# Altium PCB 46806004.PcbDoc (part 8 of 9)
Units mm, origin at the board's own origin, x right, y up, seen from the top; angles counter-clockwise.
Board outline 130 x 105 mm, 8 copper layers (Top Layer, P1-GND, L1-Signal, L2-Signal, L3-Signal, L4-Signal, P2-GND, Bottom Layer), stack 1.63 mm thick; 796 components, 496 nets, 2808 pads, 1195 vias.
Unrouted connection lines stored in the file: 1.
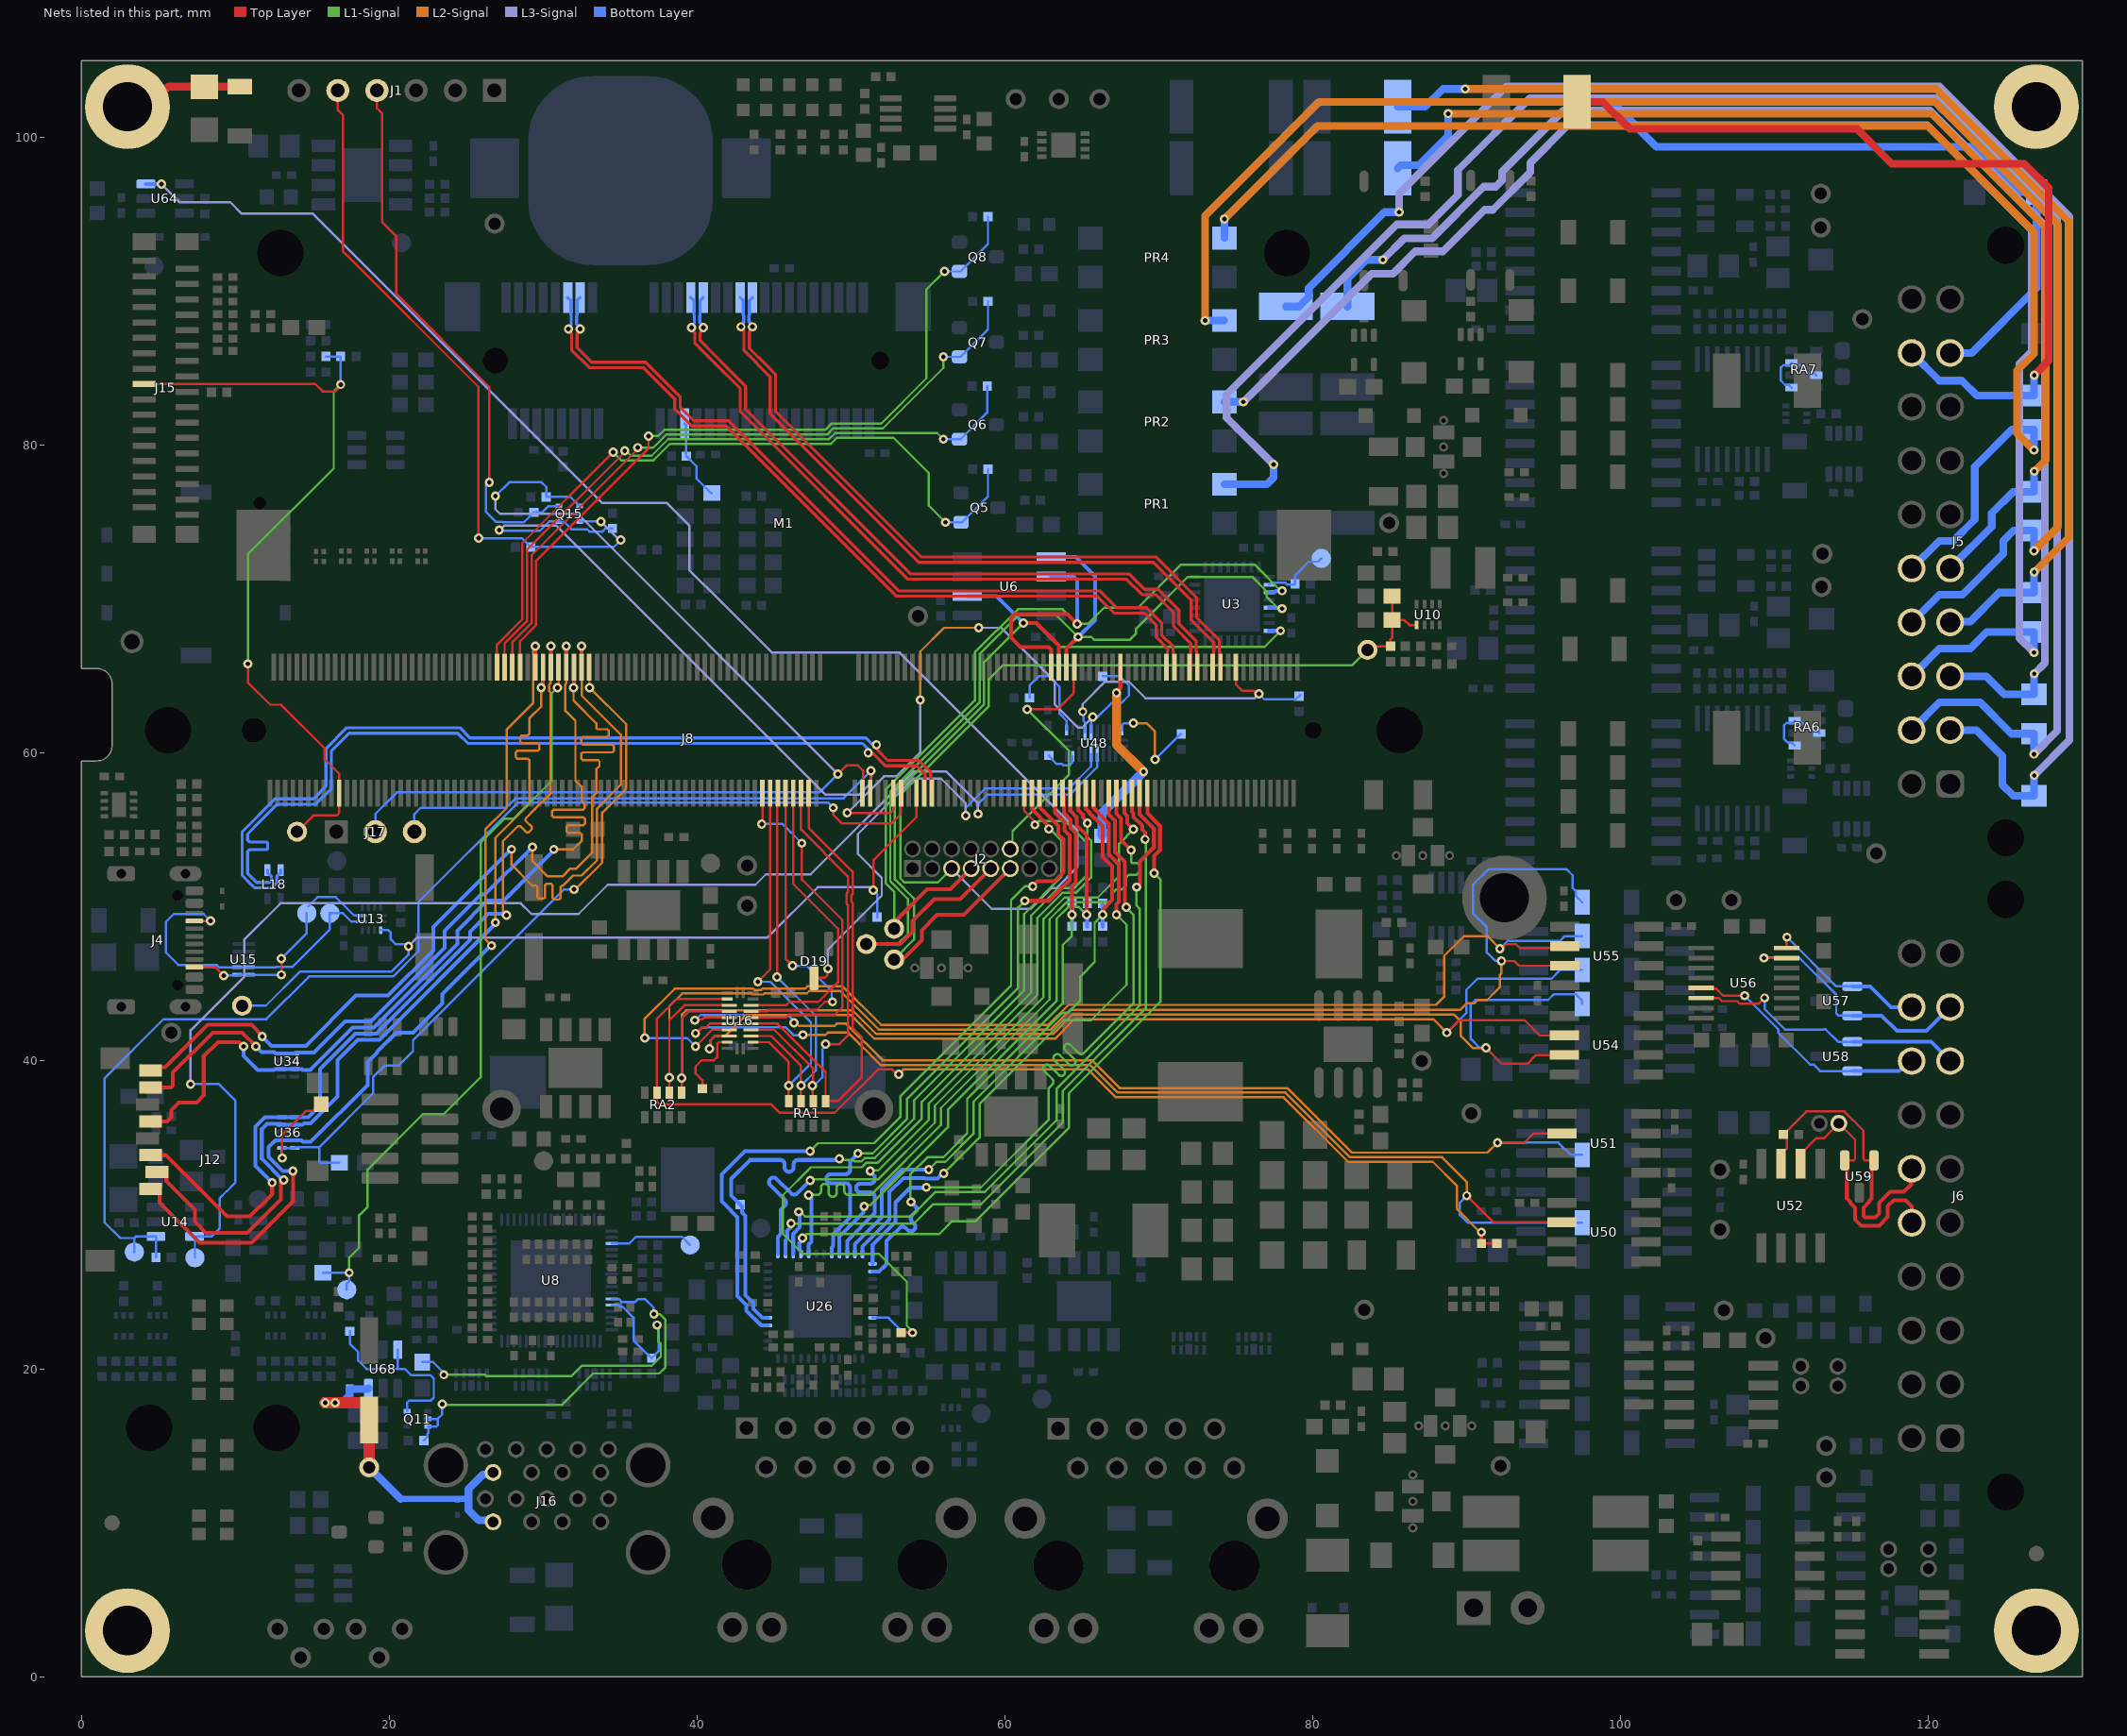
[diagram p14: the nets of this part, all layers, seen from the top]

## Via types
v1: diameter 0.6, hole 0.3, Top Layer to Bottom Layer, tented both sides, 1130 vias
v2: diameter 0.6, hole 0.3, Top Layer to Bottom Layer, 53 vias
v3: diameter 0.3, hole 0.3, Top Layer to Bottom Layer, 12 vias

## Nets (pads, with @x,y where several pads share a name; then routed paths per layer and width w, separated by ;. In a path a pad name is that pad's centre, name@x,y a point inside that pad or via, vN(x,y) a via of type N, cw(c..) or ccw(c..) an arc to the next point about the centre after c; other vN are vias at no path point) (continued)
NetR272_1: R272.1 U16.21 | length 4.8
  Top Layer w0.15: R272.1@40.35,38.2 40.35,38.75 39.9,39.2 39.9,39.65 40.3,40.05 41.1,40.05 41.325,40.275 41.325,41.125 41.425,41.225 U16.21@41.95,41.225
NetR273_2: R273.2 U48.21 | length 2.3
  Bottom Layer w0.15: R273.2@62.85,59.85 63.075,59.625 63.075,59.575 63.358,59.292 63.708,59.292 63.8,59.2 64.168,59.2 64.375,59.407 64.375,59.775 U48.21@64.4,59.8
NetR274_1: R274.1 U48.1 | length 6.3
  Bottom Layer w0.15: R274.1@61.6,63.6 61.6,64.4 62.2,65 62.85,65 63.55,64.3 63.55,62.559 64,62.109 U48.1@64,61.5
NetR275_1: R275.1 U48.10 | length 6.9
  L2-Signal w0.15: v1(68.35,61.95) 69.2,61.95 69.75,61.4 v1(69.75,59.6)
  Bottom Layer w0.15: U48.10@67.6,61.5 67.625,61.525 67.625,61.862 67.713,61.95 v1(68.35,61.95) ; v1(69.75,59.6) 71.4,61.25 R275.1@71.45,61.25
NetRA6_1: RA6.1 RA6.3 RA6.7 | length 4.5
  Bottom Layer w0.15: RA6.1@111.3,60.5 111.125,60.675 110.875,60.675 110.6,60.95 110.6,61.8 110.766,61.966 111.166,61.966 RA6.3@111.3,62.1 111.434,61.966 111.834,61.966 112.35,61.45 112.75,61.45 RA6.7@112.9,61.3
NetRA7_1: RA7.1 RA7.3 RA7.7 | length 4.5
  Bottom Layer w0.15: RA7.1@111.1,83.75 110.925,83.925 110.675,83.925 110.4,84.2 110.4,85.05 110.566,85.216 110.966,85.216 RA7.3@111.1,85.35 111.234,85.216 111.634,85.216 112.15,84.7 112.55,84.7 RA7.7@112.7,84.55
NetU8_20: U8.20 X13.1 | length 5.5
  Bottom Layer w0.15: U8.20@34.459,28.147 35.597,28.147 36.025,28.575 39.023,28.575 X13.1@39.548,28.05
OVRCRRn: R15.1 R217.2 U8.30 | length 25.9
  L1-Signal w0.15: v1(23.555,19.619) 26.231,19.619 26.325,19.525 31.825,19.525 32.5,20.2 37.05,20.2 37.65,20.8 37.65,21.639 37.475,21.814 37.475,22.775 v1(37.4,22.85)
  Bottom Layer w0.15: R217.2@22.15,20.45 22.85,20.45 23.469,19.831 23.469,19.705 v1(23.555,19.619) ; U8.30@34.459,24.147 34.486,24.12 34.925,24.12 34.998,24.047 35.151,24.047 35.873,23.325 35.873,21.845 36.758,20.961 36.789,20.961 R15.1@37.05,20.7 37.5,21.15 37.5,22.628 37.4,22.728 v1(37.4,22.85)
PCIE_CLK_N: J8.11 M1.226 | length 52.5
  Top Layer w0.2: v1(31.65,87.55) 31.65,87.442 31.85,87.242 31.85,86.205 33.005,85.05 36.505,85.05 38.55,83.005 38.55,82.35 39.65,81.25 41.9,81.25 52.954,70.196 66.009,70.196 67.105,69.1 69.055,69.1 69.825,68.33 69.825,67.54 70.575,66.79 70.575,66.624 70.55,66.599 70.55,65.65 M1.226@70.5,65.6
  Bottom Layer w0.2: J8.11@31.6,89.6 31.8,89.4 31.8,88.476 31.825,88.451 31.825,87.833 31.65,87.658 v1(31.65,87.55)
PCIE_CLK_P: J8.13 M1.228 | length 52.5
  Top Layer w0.2: v1(32.4,87.55) 32.4,87.442 32.2,87.242 32.2,86.35 32.35,86.2 33.15,85.4 36.65,85.4 38.9,83.15 38.9,82.495 39.795,81.6 42.045,81.6 53.099,70.546 66.154,70.546 67.25,69.45 69.2,69.45 70.175,68.475 70.175,67.685 70.925,66.935 70.925,66.624 70.95,66.599 70.95,65.65 M1.228@71,65.6
  Bottom Layer w0.2: v1(32.4,87.55) 32.4,87.658 32.175,87.883 32.175,88.451 32.2,88.476 32.2,89.4 J8.13@32.4,89.6
PCIE_RESET#: M1.244 R276.1 U48.4 | length 20.3
  Top Layer w0.15: M1.244@75,65.6 75.012,65.588 75.012,64.463 75.425,64.05 76.187,64.05 76.387,63.85 v1(76.5,63.85)
  L3-Signal w0.15: v1(65.05,62.7) 65.05,63.2 66.5,64.65 68.05,64.65 69.125,63.575 76.225,63.575 v1(76.5,63.85)
  Bottom Layer w0.15: v1(65.05,62.7) 65.1,62.65 65.1,62.1 65.2,62 U48.4@65.2,61.35 ; v1(76.5,63.85) 76.85,63.5 78.9,63.5 R276.1@79.169,63.769
PCIE_RESET_3V: D19.3 U48.18 | length 32.7
  Top Layer w0.15: D19.3@47.6,45.4 48.3,45.4 48.5,45.6 v1(48.5,46)
  L3-Signal w0.15: v1(48.5,46) 48.5,47.25 52,50.75 52,51.9 50.45,53.45 50.45,54.75 54.05,58.35 55.85,58.35 57.45,56.75 v1(57.45,55.95)
  Bottom Layer w0.15: v1(57.45,55.95) 57.45,56.45 58.7,57.7 64.15,57.7 65.6,59.15 U48.18@65.6,59.95
PCIE_RX_N: J8.23 M1.232 | length 46.5
  Top Layer w0.2: v1(39.65,87.65) 39.65,87.542 39.85,87.342 39.85,86.65 40.999,85.501 42.8,83.7 42.8,82.2 53.7,71.3 67.905,71.3 68.905,70.3 69.805,70.3 70.95,69.155 70.95,68.255 72.075,67.13 72.075,66.624 72.05,66.599 72.05,65.65 M1.232@72,65.6
  Bottom Layer w0.2: J8.23@39.6,89.6 39.8,89.4 39.8,88.476 39.825,88.451 39.825,87.933 39.65,87.758 v1(39.65,87.65)
PCIE_RX_P: J8.25 M1.234 | length 46.5
  Top Layer w0.2: v1(40.4,87.65) 40.4,87.542 40.2,87.342 40.2,86.795 41.144,85.851 42.031,84.964 42.147,84.847 43.15,83.845 43.15,82.345 53.845,71.65 68.05,71.65 69.05,70.65 69.95,70.65 71.3,69.3 71.3,68.4 72.425,67.275 72.425,66.624 72.45,66.599 72.45,65.65 M1.234@72.5,65.6
  Bottom Layer w0.2: v1(40.4,87.65) 40.4,87.758 40.175,87.983 40.175,88.451 40.2,88.476 40.2,89.4 J8.25@40.4,89.6
PCIE_TX_N: J8.31 M1.238 | length 45.9
  Top Layer w0.2: v1(42.85,87.7) 42.85,87.592 43.05,87.392 43.05,86.155 44.75,84.455 44.75,82.05 54.4,72.4 69.655,72.4 72.1,69.955 72.1,68.655 73.575,67.18 73.575,66.624 73.55,66.599 73.55,65.65 M1.238@73.5,65.6
  Bottom Layer w0.2: J8.31@42.8,89.6 43,89.4 43,88.476 43.025,88.451 43.025,87.983 42.85,87.808 v1(42.85,87.7)
PCIE_TX_P: J8.33 M1.240 | length 45.9
  Top Layer w0.2: v1(43.6,87.7) 43.6,87.592 43.4,87.392 43.4,86.3 44.5,85.2 44.616,85.084 45.1,84.6 45.1,82.195 54.545,72.75 69.8,72.75 72.45,70.1 72.45,68.8 73.925,67.325 73.925,66.624 73.95,66.599 73.95,65.65 M1.240@74,65.6
  Bottom Layer w0.2: v1(43.6,87.7) 43.6,87.808 43.375,88.033 43.375,88.451 43.4,88.476 43.4,89.4 J8.33@43.6,89.6
PERST#: J8.22 R146.2 R148.2 | length 5.3
  Bottom Layer w0.15: J8.22@39.2,81.4 39.3,81.3 R146.2@39.3,79.3 39.963,78.638 39.963,77.838 40.9,76.9 R148.2@40.95,76.9
PIRQ#: R10.1 U3.18 X8.1 | length 4.5
  Bottom Layer w0.15: U3.18@77.15,70.95 77.275,71.075 78.217,71.075 78.342,70.95 78.788,70.95 R10.1@78.838,71 78.838,71.543 78.882,71.587 79.734,72.44 80.34,72.44 X8.1@80.55,72.65
PR_OUT1A: D14.2 J5.3 PTC1.2 | length 108.2
  L3-Signal w0.5: v1(85.6,95.15) 85.6,96.35 92.55,103.3 96.276,103.3 120.71,103.3 129.15,94.86 129.15,60.85 v1(126.86,58.56)
  Bottom Layer w0.5: PTC1.2@78.25,89.016 79.097,89.016 79.737,89.656 79.737,90.23 84.657,95.15 v1(85.6,95.15) ; J5.3@121.4,61.5 123.1,61.5 124.8,59.8 124.8,57.95 125.515,57.235 D14.2@126.85,57.235 v1@126.85,58.55
PR_OUT1B: D14.1 J5.4 PR1.3 | length 122.4
  L3-Signal w0.5: v1(77.45,78.75) 74.4,81.8 74.4,83.3 85.45,94.35 87.5,94.35 89.425,96.275 89.425,97.875 94.1,102.55 120.483,102.55 128.35,94.683 128.35,61.45 v1(126.84,59.94)
  Bottom Layer w0.5: PR1.3@74.25,77.47 77.02,77.47 77.45,77.9 v1(77.45,78.75) ; J5.4@118.9,61.5 120.7,63.3 123.35,63.3 125.385,61.265 D14.1@126.85,61.265 v1@126.85,59.95
PR_OUT2A: D15.2 J5.5 PTC2.2 | length 91.7
  L3-Signal w0.5: v1(84.55,92.05) 85.95,93.45 87.75,93.45 91.1,96.8 91.89,96.8 92.3,97.21 92.3,97.78 96.27,101.75 120.081,101.75 127.56,94.271 127.56,65.86 v1(126.86,65.16)
  Bottom Layer w0.5: PTC2.2@82.25,89.016 82.25,90.8 83.5,92.05 v1(84.55,92.05) ; J5.5@121.4,65 123.75,65 124.915,63.835 D15.2@126.85,63.835 v1@126.85,65.15
PR_OUT2B: D15.1 J5.6 PR2.3 | length 101.7
  L3-Signal w0.5: v1@75.509,82.839 83.82,91.15 85.2,91.15 86.65,92.6 88.45,92.6 91.15,95.3 91.69,95.3 94.128,97.739 94.128,98.361 96.567,100.8 119.9,100.8 126.7,94 126.7,86.1 125.9,85.3 125.9,67.48 v1(126.84,66.54)
  Bottom Layer w0.5: PR2.3@74.26,82.82 v1(75.49,82.82) ; J5.6@118.9,65 120.7,66.8 122.7,66.8 123.765,67.865 D15.1@126.85,67.865 v1@126.85,66.55
PR_OUT3A: D16.2 J5.7 PTC3.2 | length 78.9
  L2-Signal w0.5: v1(89.9,103.15) 120.51,103.15 129.1,94.56 129.1,74 v1(126.86,71.76)
  Bottom Layer w0.5: PTC3.2@85.516,102 87.3,102 88.45,103.15 v1(89.9,103.15) ; J5.7@121.4,68.5 121.45,68.55 122.7,68.55 124.585,70.435 D16.2@126.85,70.435 v1@126.85,71.75
PR_OUT3B: D16.1 J5.8 PR3.3 | length 103.9
  L2-Signal w0.5: v1(73.01,88.1) 73.01,94.91 80.4,102.3 120.441,102.3 128.4,94.341 128.4,74.7 v1(126.84,73.14)
  Bottom Layer w0.5: v1(73.01,88.1) PR3.3@74.24,88.1 ; J5.8@118.9,68.5 120.7,70.3 122.2,70.3 124.85,72.95 124.85,73.8 125.515,74.465 D16.1@126.85,74.465 v1@126.85,73.15
PR_OUT4A: D17.2 J5.9 PTC4.2 | length 73
  L2-Signal w0.5: v1(88.8,101.55) 120.211,101.55 127.6,94.161 127.6,79.05 v1(126.86,78.31)
  Bottom Layer w0.5: PTC4.2@85.516,98 85.716,98.2 86.9,98.2 88.8,100.1 v1(88.8,101.55) ; J5.9@121.4,72 124.1,74.7 124.1,75.6 125.485,76.985 D17.2@126.85,76.985 v1@126.85,78.3
PR_OUT4B: D17.1 J5.10 PR4.3 | length 89.3
  L2-Signal w0.5: v1(74.25,94.7) 80.3,100.75 119.95,100.75 126.85,93.85 126.85,85.95 125.75,84.85 125.75,80.78 v1(126.84,79.69)
  Bottom Layer w0.5: PR4.3@74.25,93.47 v1(74.25,94.7) ; J5.10@118.9,72 120.7,73.8 121.616,73.8 123,75.184 123,78.6 125.415,81.015 D17.1@126.85,81.015 v1@126.85,79.7
PWM_3_DSI: J15.18 M1.19 R201.1 R202.2 X79.1 | length 52.4
  Top Layer w0.15: J15.18@4.081,83.978 4.092,83.989 15.201,83.989 15.69,83.5 16.5,83.5 16.85,83.85 v1(16.85,83.95) ; v1(10.825,65.8) 10.825,64.601 12.276,63.15 12.976,63.15 15.8,60.326 15.8,59.624 16.75,58.674 M1.19@16.75,57.4 16.75,56.1 16.6,55.95 15.07,55.95 X79.1@14.02,54.9
  L1-Signal w0.15: v1(10.825,65.8) 10.825,72.925 16.4,78.5 16.4,83.5 v1(16.85,83.95)
  Bottom Layer w0.15: R201.1@15.9,85.775 R202.2@16.85,85.775 v1(16.85,83.95)
PWR1: D26.1 J5.17 PTC8.2 | length 45.9
  Bottom Layer w0.5: PTC8.2@97.166,102.3 99.426,102.3 102.326,99.4 122.75,99.4 125.683,96.468 ; J5.17@121.4,86 122.8,86 127.015,90.215 D26.1@127.015,96.45 127.007,96.458 125.693,96.458
PWR2: D23.1 J5.18 PTC7.2 | length 55.9
  Top Layer w0.5: PTC7.2@97.166,102.3 98.838,102.3 100.588,100.55 115.35,100.55 117.6,98.3 126.218,98.3 127.8,96.718 127.8,85.5 v1(126.86,84.56)
  Bottom Layer w0.5: J5.18@118.9,86 120.7,84.2 122.166,84.2 123.131,83.235 D23.1@126.85,83.235 v1@126.85,84.55
PWR_1V8: L3.2 M1.214 | length 12.9
  Top Layer w0.3: v1(67.25,63.925) 67.25,64.006 67.5,64.256 M1.214@67.5,65.6
  L2-Signal w0.6: v1(67.25,63.925) 67.25,60.55 v1(69,58.8)
  Bottom Layer w0.6: L3.2@66.3,54.64 66.3,56.1 v1(69,58.8)
PWR_EN: J2.5 R5.1 R6.1 R27.2 U10.1 U64.3 X15.1 | length 143.5
  Top Layer w0.15: X15.1@83.55,66.715 83.77,66.935 84.197,66.935 84.213,66.95 85.05,66.95 85.05,67.4 85.15,67.5 R6.1@85.15,68.65 85.945,68.65 86.27,68.325 U10.1@86.75,68.325 ; R6.1@85.15,68.7 R5.1@85.15,70.2
  L1-Signal w0.15: J2.5@56.535,52.505 55.63,51.6 53.482,51.6 53.2,51.882 53.2,57.3 58.95,63.05 58.95,64.8 59.85,65.7 82.535,65.7 X15.1@83.55,66.715
  L3-Signal w0.15: v1(5.2,96.978) 6.375,95.803 9.667,95.803 10.42,95.05 15.05,95.05 33.85,76.25 38.042,76.25 39.5,74.792 39.5,71.9 41.6,69.8 44.875,66.525 53.174,66.525 64.7,54.999 64.7,52.592 63.341,51.233 63.025,51.233 61.678,49.885 59.155,49.885 J2.5@56.535,52.505
  Bottom Layer w0.25: U64.3@4.195,96.978 v1(5.2,96.978)
PWR_EN#: Q11.5 Q11.6 R16.1 U8.29 | length 26.9
  L1-Signal w0.15: v1(23.45,17.7) 23.5,17.65 31.2,17.65 33.25,19.7 37.543,19.7 37.95,20.107 37.95,23.2 37.61,23.54 37.233,23.54 v1(37.2,23.573)
  Bottom Layer w0.15: R16.1@22.25,15.35 22.475,15.575 22.475,15.786 22.55,15.861 22.55,16.225 Q11.6@22.525,16.25 23.062,16.25 23.15,16.338 23.15,16.75 ; Q11.5@22.525,16.75 23.15,16.75 ; v1(23.45,17.7) 23.45,17.05 23.15,16.75 ; U8.29@34.459,24.547 34.486,24.52 34.949,24.52 35.11,24.359 35.984,24.359 36.15,24.525 36.635,24.525 37.172,23.988 37.172,23.601 v1(37.2,23.573)
PWR_USB: Q11.3 R223.1 U68.3 | length 12.4
  Bottom Layer w0.15: R223.1@17.45,22.45 17.45,21.626 17.975,21.101 17.975,20.553 18.528,20 20.561,20 ; U68.3@20.561,21.255 20.561,20 ; Q11.3@21.175,17.25 21.175,17.816 21.308,17.949 22.717,17.949 22.9,18.132 22.9,19.368 22.668,19.6 21.411,19.6 21.011,20 20.561,20
REL1: M1.60 Q5.1 R106.2 | length 48.2
  Top Layer w0.15: M1.60@27,65.6 27,67.05 28.65,68.7 28.65,73.65 v1(34.55,79.55)
  L1-Signal w0.15: v1(34.55,79.55) 35.075,79.025 37.174,79.025 38.249,80.1 48.7,80.1 49.1,80.5 52.75,80.5 55.05,78.2 55.05,76.088 v1(56.138,75)
  Bottom Layer w0.15: v1@56.139,74.999 Q5.1@57.147,74.999 57.222,74.999 58.897,76.674 R106.2@58.897,78.449
REL2: M1.62 Q6.1 R107.2 | length 44.2
  Top Layer w0.15: M1.62@27.5,65.6 27.5,67.126 28.95,68.576 28.95,73.208 35.3,79.558 v1(35.3,79.65)
  L1-Signal w0.15: v1(35.3,79.65) 35.392,79.65 35.717,79.325 37.049,79.325 38.124,80.4 48.576,80.4 48.976,80.8 55.6,80.8 v1(56,80.4)
  Bottom Layer w0.15: v1@56.001,80.399 Q6.1@57.047,80.399 57.122,80.399 58.847,82.124 R107.2@58.847,83.849
REL3: M1.64 Q7.1 R108.2 | length 45.8
  Top Layer w0.15: M1.64@28,65.6 28,67.201 29.25,68.451 29.25,72.858 36.15,79.758 v1(36.15,79.85)
  L1-Signal w0.15: v1(36.15,79.85) 37.15,79.85 38,80.7 48.451,80.7 48.851,81.1 52.074,81.1 56,85.026 v1(56,85.75)
  Bottom Layer w0.15: v1@56.001,85.749 Q7.1@57.047,85.749 57.122,85.749 58.897,87.524 R108.2@58.897,89.349
  Bottom Layer w0.25: v1(56,85.75) v1@56.001,85.749
REL4: M1.66 Q8.1 R109.2 | length 50.8
  Top Layer w0.15: M1.66@28.5,65.6 28.5,67.277 29.55,68.327 29.55,72.508 36.85,79.808 v1(36.85,80.6)
  L1-Signal w0.15: v1(36.85,80.6) 37.476,80.6 37.876,81 48.327,81 48.727,81.4 51.95,81.4 54.9,84.35 54.9,90.125 v1(56.075,91.3)
  Bottom Layer w0.15: v1@56.076,91.299 Q8.1@57.047,91.299 57.122,91.299 58.897,93.074 58.897,94.027 R109.2@58.897,94.849
RGMII.RGMII_INT#: M1.189 R221.1 U26.44 | length 59.5
  Top Layer w0.15: R221.1@53.25,22.35 53.255,22.355 v1(53.995,22.355) ; M1.189@61.25,57.4 61.25,56.25 61.95,55.55 v1(61.95,55.35)
  L1-Signal w0.15: v1(53.995,22.355) 53.995,22.445 53.625,22.815 53.625,25.667 51.817,27.475 46.883,27.475 45.575,28.783 45.575,31.275 47.4,33.1 50.717,33.1 51.017,33.4 51.75,33.4 54.6,36.25 54.6,37.35 61.7,44.45 61.7,49.45 63.5,51.25 64.5,51.25 65.3,52.05 65.3,54.2 63.9,55.6 62.2,55.6 v1(61.95,55.35)
  Bottom Layer w0.15: U26.44@51.4,23.325 52.435,23.325 53.41,22.35 53.991,22.35 v1(53.995,22.355)
RGMII.RGMII_MDC: M1.193 U26.16 | length 51.5
  Top Layer w0.25: v1(61.8,51.35) 62.13,51.68 63.227,51.68 63.8,52.253 63.8,54.4 63.475,54.725 63.475,55.261 63.436,55.3 63.436,55.313 62.5,56.25 62.486,56.25 62.275,56.461 62.275,57.375 M1.193@62.25,57.4
  L1-Signal w0.15: v1(47.35,34.15) 47.864,34.664 51.514,34.664 53.2,36.35 53.2,37.7 60.4,44.9 60.4,50.45 61.3,51.35 v1(61.8,51.35)
  Bottom Layer w0.25: U26.16@44.6,22.825 44.164,22.825 43.2,23.789 43.2,24.146 42.625,24.721 42.625,29.861 42.225,30.261 42.225,30.275 41.6,30.9 41.6,32.65 43.1,34.15 v1(47.35,34.15)
RGMII.RGMII_MDIO: M1.191 R220.1 U26.17 | length 50.9
  Top Layer w0.25: M1.191@61.75,57.4 61.75,56.363 62.861,55.251 v1(62.861,55.075)
  L1-Signal w0.15: v1(49.25,33.65) 49.325,33.575 50.133,33.575 50.233,33.475 50.667,33.475 50.892,33.7 51.55,33.7 54.1,36.25 54.1,37.45 61.25,44.6 61.25,49.55 63.66,51.96 63.66,54.34 62.925,55.075 v1(62.861,55.075)
  Bottom Layer w0.25: U26.17@44.6,23.325 44.23,23.325 43.65,23.905 43.65,24.3 43.15,24.8 43.15,29.95 42.928,30.172 42.928,30.547 42.211,31.264 42.211,32.35 43.436,33.575 44.695,33.575 45.4,33.575 cw(c45.4,33.285) 45.69,33.285 45.69,33.096 ccw(c45.98,33.096) 46.27,33.096 46.27,33.285 cw(c46.56,33.285) 46.56,33.575 47.456,33.575 49.175,33.575 v1(49.25,33.65)
RGMII.RGMII_RX_CTRL: M1.199 R118.2 R120.1 U26.38 | length 40.6
  Top Layer w0.25: M1.199@63.75,57.4 63.825,57.325 63.825,56.119 64.275,55.669 64.275,55.146 64.6,54.821 64.6,51.589 64.35,51.339 v1(64.35,49.5)
  L1-Signal w0.15: v1(53.9,30.85) 53.85,30.9 53.85,32.635 54.968,33.753 56.003,33.753 57.55,35.3 57.55,37.55 63.75,43.75 63.75,47.528 64.35,48.128 v1(64.35,49.5)
  Bottom Layer w0.25: U26.38@51.4,26.325 51.825,26.325 52.299,26.799 52.299,28.306 52.636,28.643 52.643,28.643 52.653,28.653 53.151,29.151 cw(c53.356,28.946) 53.561,29.151 53.683,29.03 ccw(c53.888,29.235) 54.093,29.03 ccw(c53.888,29.235) 54.093,29.44 53.972,29.561 cw(c54.177,29.767) 53.972,29.972 54.271,30.271 54.271,30.473 54.271,30.479 v1(53.9,30.85) ; R118.2@64.35,48.75 v1(64.35,49.5) R120.1@64.35,50.25
RGMII.RGMII_RXC: M1.197 U26.32 | length 40.8
  Top Layer w0.25: v1(61.291,50.41) 62.855,50.41 64.2,51.755 64.2,54.655 63.875,54.98 63.875,55.504 63.25,56.129 M1.197@63.25,57.4
  L1-Signal w0.15: v1(50.45,34) 51.4,34 53.65,36.25 53.65,37.55 60.85,44.75 60.85,49.969 v1(61.291,50.41)
  Bottom Layer w0.25: U26.32@48.75,27.475 48.75,27.9 48.845,27.995 48.845,28.761 49.933,29.848 49.933,30.493 49.933,31.778 ccw(c49.643,31.778) 49.643,32.068 48.688,32.068 cw(c48.688,32.358) 48.688,32.648 49.643,32.648 ccw(c49.643,32.938) 49.933,32.938 49.933,33.435 49.933,33.483 v1(50.45,34)
RGMII.RGMII_RXD_0: M1.201 R114.2 R115.1 U26.33 | length 40.2
  Top Layer w0.25: M1.201@64.25,57.4 64.25,56.26 64.675,55.835 64.675,55.312 65.3,54.687 v1(65.3,49.5)
  L1-Signal w0.15: v1(50.85,30.55) 50.921,30.621 51.221,30.621 56.3,35.7 56.3,36.85 63.35,43.9 63.35,49.242 64.133,50.025 64.775,50.025 v1(65.3,49.5)
  Bottom Layer w0.25: U26.33@49.25,27.475 49.25,28.6 50.798,30.148 50.798,30.498 v1(50.85,30.55) ; R114.2@65.35,48.75 65.35,49.45 v1(65.3,49.5) 65.3,50.2 R115.1@65.35,50.25
RGMII.RGMII_RXD_1: M1.203 U26.34 | length 39.8
  Top Layer w0.25: M1.203@64.75,57.4 64.75,56.326 65.075,56.001 65.075,55.82 65.35,55.545 v1(65.35,55.45)
  L1-Signal w0.15: v1(51.25,32.85) 51.3,32.9 51.775,32.9 55.05,36.175 55.05,37.25 62.1,44.3 62.1,49.3 63.725,50.925 64.599,50.925 65.6,51.926 65.6,54.324 65.35,54.574 v1(65.35,55.45)
  Bottom Layer w0.25: U26.34@49.75,27.475 49.75,28.319 51.55,30.119 51.55,31.044 51.55,31.169 ccw(c51.26,31.169) 51.26,31.459 50.623,31.459 cw(c50.623,31.749) 50.623,32.039 51.26,32.039 ccw(c51.26,32.329) 51.55,32.329 51.55,32.529 51.25,32.829 51.25,32.842 v1(51.25,32.85)
RGMII.RGMII_RXD_2: M1.205 R116.2 R117.2 U26.35 | length 40.6
  Top Layer w0.25: M1.205@65.25,57.4 65.25,56.391 65.475,56.166 65.475,56.138 66.35,55.263 66.35,53.255 66.95,52.655 66.95,50.454 66.4,49.904 66.4,49.55 v1(66.35,49.5)
  L1-Signal w0.15: v1(55.05,32.95) 55.553,33.453 56.127,33.453 57.95,35.276 57.95,37.35 63.75,43.15 64.1,43.15 64.9,43.95 64.9,45.5 65.829,46.429 65.829,48.979 v1(66.35,49.5)
  Bottom Layer w0.25: U26.35@50.25,27.475 50.25,28.1 52,29.85 52,31.65 53.3,32.95 v1(55.05,32.95) ; R116.2@66.35,48.75 v1(66.35,49.5) R117.2@66.35,50.25
RGMII.RGMII_RXD_3: M1.207 U26.36 | length 40.5
  Top Layer w0.25: M1.207@65.75,57.4 65.75,56.457 65.875,56.332 65.875,56.304 66.75,55.429 66.75,53.421 67.4,52.771 67.4,50.338 67.25,50.188 v1(67.25,49.5)
  L1-Signal w0.15: v1(56.025,32.7) 58.35,35.025 58.35,37.2 63.8,42.65 65.6,42.65 67.9,44.95 67.9,48.85 v1(67.25,49.5)
  Bottom Layer w0.25: U26.36@50.75,27.475 50.75,27.95 52.5,29.7 52.5,31.5 53.4,32.4 54.787,32.4 54.812,32.375 55.605,32.375 55.93,32.7 v1(56.025,32.7)
RGMII.RGMII_TX_CTRL: M1.211 U26.37 | length 47.5
  Top Layer w0.25: M1.211@66.75,57.4 66.75,55.995 67.15,55.595 67.15,53.586 67.8,52.936 67.8,50.075 v1(67.875,50)
  L1-Signal w0.15: v1(54.9,31.8) 58.45,31.8 62.85,36.2 62.85,38.25 63.033,38.433 63.086,38.486 ccw(c62.916,38.656) 63.086,38.825 62.548,39.363 ; 62.548,39.363 cw(c62.718,39.533) 62.548,39.702 cw(c62.718,39.533) 62.888,39.702 63.488,39.102 ccw(c63.658,39.272) 63.828,39.102 ccw(c63.658,39.272) 63.828,39.442 63.227,40.042 cw(c63.397,40.212) 63.227,40.381 cw(c63.397,40.212) 63.567,40.381 64.167,39.781 ccw(c64.337,39.951) 64.507,39.781 ccw(c64.337,39.951) 64.507,40.121 63.907,40.721 cw(c64.076,40.891) 63.907,41.061 cw(c64.076,40.891) 64.246,41.061 64.784,40.523 ccw(c64.953,40.693) 65.123,40.523 65.426,40.826 68.35,43.75 68.35,49.5 67.875,49.975 v1(67.875,50)
  Bottom Layer w0.25: U26.37@51.4,26.825 51.4,28.034 52.9,29.534 52.9,30.817 53.85,31.767 54.867,31.767 v1(54.9,31.8)
RGMII.RGMII_TXC: M1.213 U26.29 | length 46.6
  Top Layer w0.25: M1.213@67.25,57.4 67.25,56.06 67.55,55.76 67.55,54.35 v1(68.2,53.7)
  L1-Signal w0.15: v1(47.25,31.3) 47.722,31.3 47.797,31.3 ccw(c47.797,31.553) 48.05,31.553 48.05,31.772 cw(c48.303,31.772) 48.303,32.025 cw(c48.303,31.772) 48.556,31.772 48.556,31.428 ccw(c48.808,31.428) 48.808,31.175 ccw(c48.808,31.428) 49.061,31.428 49.061,31.772 cw(c49.314,31.772) 49.314,32.025 cw(c49.314,31.772) 49.567,31.772 49.567,31.553 ccw(c49.82,31.553) 49.82,31.3 51.023,31.3 51.3,31.3 55.85,35.85 55.85,36.95 62.9,44 62.9,49.217 64.008,50.325 66.773,50.325 66.988,50.54 66.988,50.913 67.213,51.138 67.586,51.138 67.85,51.402 67.85,51.9 68.052,52.102 68.55,52.102 68.8,52.352 68.8,52.65 68.6,52.85 68.288,52.85 68.2,52.938 v1(68.2,53.7)
  Bottom Layer w0.25: U26.29@47.25,27.475 47.25,28.087 47.425,28.262 47.425,31.125 v1(47.25,31.3)
RGMII.RGMII_TXD_0: M1.221 U26.28 | length 46.1
  Top Layer w0.25: M1.221@69.25,57.4 69.25,56.095 70.075,55.27 70.075,53.709 69.7,53.334 v1(69.7,52.2)
  L1-Signal w0.15: v1(46.85,28.5) 46.863,28.5 47.113,28.75 55.725,28.75 56.575,29.6 58.1,29.6 64.15,35.65 64.15,37.9 70.1,43.85 70.1,51.8 v1(69.7,52.2)
  Bottom Layer w0.25: U26.28@46.745,27.65 46.65,27.745 46.65,28.205 46.85,28.405 v1(46.85,28.5)
RGMII.RGMII_TXD_1: M1.219 U26.27 | length 46.8
  Top Layer w0.25: v1(68.55,51.3) 68.775,51.525 68.775,52.975 69.675,53.875 69.675,55.104 68.75,56.029 M1.219@68.75,57.4
  L1-Signal w0.15: v1(46.6,30.2) 46.722,30.2 47.022,29.9 53.9,29.9 55.5,31.5 58.7,31.5 63.35,36.15 63.35,38.2 68.75,43.6 68.75,49.9 68.55,50.1 v1(68.55,51.3)
  Bottom Layer w0.25: U26.27@46.25,27.475 46.25,28.787 46.675,29.212 46.675,29.688 46.657,29.707 46.657,30.143 v1(46.6,30.2)
RGMII.RGMII_TXD_2: M1.217 U26.26 | length 46.5
  Top Layer w0.25: M1.217@68.25,57.4 68.25,56.192 68.35,56.092 68.35,55.863 68.925,55.288 68.925,55.025 69.1,54.85 v1(69.1,54.4)
  L1-Signal w0.15: v1(46.1,29.45) 54.1,29.45 55.35,30.7 58.45,30.7 63.75,36 63.75,38.05 69.143,43.443 69.143,54.357 v1(69.1,54.4)
  Bottom Layer w0.25: U26.26@45.75,27.475 45.75,28.355 45.85,28.455 45.85,28.953 46.1,29.203 v1(46.1,29.45)
RGMII.RGMII_TXD_3: M1.215 U26.25 | length 46.8
  Top Layer w0.25: M1.215@67.75,57.4 67.75,56.126 67.95,55.926 67.95,55.45 v1(68.35,55.05)
  L1-Signal w0.15: v1(47.35,32.25) 47.425,32.325 51.775,32.325 55.45,36 55.45,37.1 62.5,44.15 62.5,49.241 63.884,50.625 66.025,50.625 67.416,52.016 67.416,54.116 v1(68.35,55.05)
  Bottom Layer w0.25: U26.25@45.25,27.475 45.25,28.577 45.45,28.777 45.45,30.35 45.603,30.503 45.692,30.592 ccw(c45.487,30.797) 45.692,31.002 44.761,31.933 cw(c44.966,32.138) 44.761,32.343 cw(c44.966,32.138) 45.171,32.343 46.102,31.412 ccw(c46.307,31.617) 46.512,31.412 v1(47.35,32.25)
RS232_CTS: J6.18 U56.8 U57.1 | length 10.7
  Top Layer w0.15: U56.8@110.775,47.343 110.775,48.025 v1(110.8,48.05)
  Bottom Layer w0.15: v1(110.8,48.05) 114,44.85 U57.1@115.05,44.85
  Bottom Layer w0.25: U57.1@115.05,44.85 116.2,44.85 117.55,43.5 J6.18@118.9,43.5
RS232_RTS: J6.17 U56.7 U57.2 | length 16.9
  Top Layer w0.15: v1(109.3,46.7) 110.768,46.7 U56.7@110.775,46.693
  Bottom Layer w0.15: v1(109.3,46.7) 111.612,46.7 114,44.312 114,43.1 114.15,42.95 U57.2@115.05,42.95
  Bottom Layer w0.25: U57.2@115.05,42.95 116.95,42.95 117.95,41.95 119.85,41.95 J6.17@121.4,43.5
RS232_RX: J6.16 U56.13 U58.2 | length 16.3
  Top Layer w0.15: U56.13@105.225,44.743 105.255,44.713 106.187,44.713 106.65,44.25 v1(108.05,44.25)
  Bottom Layer w0.15: v1(108.05,44.25) 110.246,42.054 110.246,41.824 112.295,39.775 112.525,39.775 112.95,39.35 U58.2@115.05,39.35
  Bottom Layer w0.25: U58.2@115.05,39.35 118.083,39.35 118.733,40 J6.16@118.9,40
RS232_TX: J6.15 U56.14 U58.1 | length 18.6
  Top Layer w0.15: U56.14@105.225,44.093 106.383,44.093 106.58,43.896 107.555,43.896 107.725,43.725 108.975,43.725 v1(109.35,44.1)
  Bottom Layer w0.15: v1(109.35,44.1) 109.35,43.374 110.682,42.042 113.167,42.042 113.186,42.061 113.311,42.061 114.122,41.25 U58.1@115.05,41.25
  Bottom Layer w0.25: U58.1@115.05,41.25 120.15,41.25 J6.15@121.4,40
RS485_N: J6.12 R190.1 U52.7 U59.1 | length 20.4
  Top Layer w0.15: U52.7@110.415,33.33 110.415,33.965 110.657,34.208 110.687,34.208 110.788,34.308 110.788,34.915 110.788,35.003 R190.1@110.563,35.228 112.06,36.725 114.525,36.725 115.775,35.475 115.775,33.638 115.863,33.55 U59.1@116.45,33.55 U59.1@116.31,33.41
  Top Layer w0.25: U59.1@116.31,33.41 116.31,31.079 116.15,30.92 116.15,30.849 115.775,30.474 115.775,29.938 115.863,29.85 116.55,29.85 116.8,30.1 116.8,30.8 117.5,31.5 118.396,31.5 118.858,31.963 118.858,32.958 J6.12@118.9,33
RS485_P: J6.10 J14.2 U52.6 U59.2 | length 17.7
  Top Layer w0.15: U52.6@111.685,33.33 111.685,33.965 112.72,35 113.22,35 J14.2@114.17,35.95 115.225,34.895 115.225,33.638 115.137,33.55 U59.2@114.55,33.55 U59.2@114.69,33.41
  Top Layer w0.25: U59.2@114.69,33.41 114.69,31.08 114.925,30.845 114.925,30.774 115.225,30.474 115.225,29.71 115.635,29.3 116.778,29.3 117.35,29.872 117.35,30.572 117.728,30.95 118.5,30.95 118.9,30.55 J6.10@118.9,29.5
SD1_CD#: J12.9 M1.84 R157.1 U36.5 U36.6 | length 51.7
  Top Layer w0.15: v1(13.05,33.7) 13.05,35.22 14.59,36.76 15.188,36.76 15.587,37.16 J12.9@15.587,37.185 ; M1.84@33,65.6 33,64.275 v1(33.025,64.25)
  L2-Signal w0.15: v1(32,51.15) 32.1,51.15 33.84,52.89 33.84,56.14 35.4,57.7 35.4,61.875 v1(33.025,64.25)
  Bottom Layer w0.15: v1(13.05,33.7) 13.05,34.333 U36.6@13.033,34.35 U36.5@13.867,34.35 13.917,34.4 15.453,34.4 ; R157.1@16.766,33.4 15.541,33.4 15.453,33.488 15.453,34.4 ; v1(32,51.15) 31.358,51.15 21.55,41.342 21.55,40.65 20.6,39.7 19.7,39.7 18.95,38.95 18.95,37.897 15.453,34.4
SD1_CLK: J12.5 M1.78 U34.4 U34.7 | length 60.2
  Top Layer w0.25: J12.5@4.503,36.085 5.585,36.085 5.85,36.35 5.85,36.8 6.35,37.3 7.5,37.3 7.95,37.75 7.95,40.3 8.875,41.225 10.275,41.225 v1(10.55,40.95) ; M1.78@31.5,65.6 v1(31.5,66.95)
  L2-Signal w0.15: v1(30.7,53.75) 31.95,53.75 32.5,54.3 32.5,54.65 32.5,54.725 32.4,54.825 31.625,54.825 31.525,54.925 31.525,55.225 31.625,55.325 32.619,55.325 32.719,55.425 32.719,55.725 32.619,55.825 30.686,55.825 30.586,55.925 30.586,56.225 30.686,56.325 32.6,56.325 32.7,56.425 32.7,56.725 32.6,56.825 32.5,56.925 32.5,57.583 32.5,57.819 32.1,58.219 32.1,62.1 31.45,62.75 31.45,64.467 31.5,64.517 v1(31.5,66.95)
  Bottom Layer w0.25: v1(10.55,40.95) 10.55,40.35 11.475,39.425 12.538,39.425 12.601,39.487 U34.7@13.008,39.488 14.312,39.488 14.387,39.412 14.863,39.412 17.63,42.179 18.997,42.179 24.423,47.606 24.423,48.473 26.375,50.425 27.454,50.425 30.7,53.671 v1(30.7,53.75)
SD1_CMD: J12.3 M1.74 U36.1 U36.10 | length 60.4
  Top Layer w0.25: J12.3@4.503,33.885 5.493,33.885 9.478,29.9 10.95,29.9 12.4,31.35 v1(12.4,32.1) ; M1.74@30.5,65.6 v1(30.5,66.95)
  L2-Signal w0.15: v1(27.621,49.479) 27.621,49.555 27.384,49.792 27.384,54.277 27.965,54.857 28.372,55.264 28.513,55.264 28.915,54.862 29.056,54.862 29.268,55.074 29.268,55.216 28.867,55.618 28.867,55.759 29.47,56.363 30.5,57.392 30.5,63.933 30.4,64.033 30.4,64.467 30.5,64.567 v1(30.5,66.95)
  Bottom Layer w0.25: v1(12.4,32.1) 11.3,33.2 11.3,35.729 11.921,36.35 U36.10@13.033,36.35 14.734,36.35 15.5,37.116 15.5,39.484 17.796,41.779 19.162,41.779 25.253,47.87 25.253,48.403 26.425,49.575 27.525,49.575 v1(27.621,49.479)
SD1_D0: J12.7 M1.80 U34.2 U34.9 | length 59.7
  Top Layer w0.25: J12.7@4.503,38.285 5.835,38.285 5.95,38.4 5.95,39.25 8.55,41.85 10.463,41.85 11.346,40.967 v2(11.346,40.946) ; v1(31.975,64.25) 32,64.275 M1.80@32,65.6
  L2-Signal w0.15: v1(29.3,53.9) 29.3,53 30.3,52 31.271,52 31.771,52.5 32.15,52.5 33.2,53.55 33.2,57.15 33.45,57.4 33.45,58.233 33.45,58.955 33.55,59.055 33.563,59.055 33.663,59.155 33.663,59.455 33.563,59.555 32.576,59.555 32.476,59.655 32.476,59.955 32.576,60.055 34.499,60.055 34.599,60.155 34.599,60.455 34.499,60.555 32.576,60.555 32.476,60.655 32.476,60.955 32.576,61.055 34.171,61.055 34.271,61.155 34.271,61.455 34.171,61.555 33.55,61.555 33.45,61.655 33.45,61.73 33.45,61.941 31.975,63.416 v1(31.975,64.25)
  Bottom Layer w0.25: v2(11.346,40.946) 11.717,40.575 12.538,40.575 12.626,40.488 U34.9@13.008,40.488 U34.2@13.842,40.488 13.917,40.562 15.112,40.562 17.129,42.579 18.831,42.579 23.6,47.349 23.6,48.45 25.975,50.825 26.225,50.825 v1(29.3,53.9)
SD1_D1: J12.8 M1.82 U34.1 U34.10 | length 59.5
  Top Layer w0.25: J12.8@4.503,39.385 4.726,39.609 5.459,39.609 8.2,42.35 11.05,42.35 11.753,41.647 v1(11.753,41.6) ; M1.82@32.5,65.6 v1(32.5,66.95)
  L2-Signal w0.15: v1(27.95,53.75) 27.95,52.75 29.173,51.527 29.3,51.4 29.525,51.4 29.625,51.3 29.625,50.65 29.725,50.55 30.025,50.55 30.125,50.65 30.125,51.417 30.225,51.517 30.525,51.517 30.625,51.417 30.625,50.587 30.725,50.487 31.025,50.487 31.125,50.587 31.125,51.3 31.225,51.4 31.3,51.4 31.302,51.4 31.952,52.05 32.5,52.05 33.5,53.05 33.5,56.4 35.05,57.95 35.05,61.2 32.5,63.75 v1(32.5,66.95)
  Bottom Layer w0.25: v1(11.753,41.6) 12.365,40.987 U34.10@13.008,40.987 U34.1@13.842,40.987 14.587,40.987 17.85,44.25 19.936,44.25 22.859,47.173 22.859,48.709 27.9,53.75 v1(27.95,53.75)
SD1_D2: J12.1 M1.70 U36.4 U36.7 | length 60.3
  Top Layer w0.25: J12.1@4.503,31.685 4.818,31.685 5.093,31.41 5.093,30.807 7.7,28.2 11.05,28.2 13.75,30.9 v1(13.75,32.85) ; M1.70@29.5,65.6 v1(29.5,66.95)
  L2-Signal w0.15: v1(26.65,47.5) 26.25,47.9 26.25,55.05 27.65,56.45 27.65,61.55 29.35,63.25 29.35,66.678 29.5,66.828 v1(29.5,66.95)
  Bottom Layer w0.25: v1(13.75,32.85) 13.087,32.85 12.168,33.768 12.168,34.405 12.613,34.85 U36.7@13.033,34.85 U36.4@13.867,34.85 14.3,34.85 14.4,34.75 14.906,34.75 18.6,38.444 18.6,39.94 19.212,40.552 19.212,40.599 20.463,41.85 21.563,41.85 23.45,43.737 23.45,44.348 26.602,47.5 v1(26.65,47.5)
SD1_D3: J12.2 M1.72 U36.2 U36.9 | length 60.4
  Top Layer w0.25: J12.2@4.902,32.785 5.252,32.785 5.527,32.51 5.527,32.199 7.377,30.35 7.377,29.573 8.1,28.85 10.8,28.85 12.975,31.025 12.975,32.1 v1(13.15,32.275) ; v1(29.875,64.25) 29.875,64.345 29.975,64.445 29.975,65.575 M1.72@30,65.6
  L2-Signal w0.15: v2(26.9,49) 26.9,54.5 29.1,56.7 29.1,59.475 29.1,59.55 29,59.65 28.318,59.65 28.218,59.75 28.218,60.05 28.318,60.15 29.641,60.15 29.741,60.25 29.741,60.55 29.641,60.65 28.61,60.65 28.51,60.75 28.51,61.05 28.61,61.15 29,61.15 29.1,61.25 29.1,61.999 29.1,62.25 29.875,63.025 v1(29.875,64.25)
  Bottom Layer w0.25: v1(13.15,32.275) 13.096,32.275 11.725,33.646 11.725,35.588 12.062,35.925 12.958,35.925 U36.9@13.033,35.85 14.362,35.85 14.462,35.95 14.9,35.95 16.65,37.7 16.65,40.068 17.961,41.379 19.372,41.379 26.9,48.907 v2(26.9,49)
SD1_PWR_EN: M1.76 R155.2 X56.1 | length 49
  Top Layer w0.15: v1(30.925,64.25) 31,64.325 M1.76@31,65.6
  L1-Signal w0.15: v1(17.4,26.25) 17.4,27.226 18.05,27.876 18.05,29.976 18.6,30.526 18.6,32.95 22.2,36.55 23.55,36.55 25.95,38.95 25.95,54.2 27.5,55.75 28.1,55.75 30.55,58.2 30.55,63.875 v1(30.925,64.25)
  Bottom Layer w0.15: R155.2@15.7,26.25 v1(17.4,26.25) 17.4,25.7 17.25,25.55 X56.1@17.25,25.15
SHLD: C102.2 H1.0 H2.0 H3.0 H4.0 R55.1 | length 7.8
  Top Layer w0.5: H2.0@3,102 4.353,102 5.653,103.3 C102.2@8,103.3 R55.1@10.3,103.3
SPI_CLK: J2.7 M1.196 U3.19 U6.6 X7.1 | length 66.8
  Top Layer w0.25: X7.1@52.8,48.6 52.8,49 54.95,51.15 56.45,51.15 J2.7@57.805,52.505 ; M1.196@63,65.6 63,66.75 62.85,66.9 61,66.9 60.4,67.5 60.4,68.8 60.65,69.05 64.05,69.05 v1(64.7,68.4)
  L1-Signal w0.15: X7.1@52.8,48.6 52.8,51.001 52.25,51.551 52.25,57.623 58.05,63.423 58.05,66.55 60.85,69.35 63.75,69.35 v1(64.7,68.4) 65.4,68.4 66.45,69.45 68.65,69.45 71.45,72.25 76.225,72.25 77.925,70.55 v1(78,70.55)
  Bottom Layer w0.25: U6.6@63.017,71.481 64.431,71.481 64.45,71.5 64.7,71.25 v1(64.7,68.4) ; U3.19@77.15,70.45 77.5,70.45 77.6,70.55 v1(78,70.55)
SPI_CS: J2.12 M1.202 | length 16.9
  Top Layer w0.15: v1(61.45,62.85) 63.4,62.85 64.475,63.925 64.475,65.575 M1.202@64.5,65.6
  L1-Signal w0.15: J2.12@60.345,53.775 60.494,53.923 60.494,54.944 64.163,58.613 64.163,60.137 v1(61.45,62.85)
SPI_MISO: J2.11 M1.198 U3.24 U6.2 X4.1 | length 63.9
  Top Layer w0.25: X4.1@52.8,46.6 53.35,46.6 54.6,47.85 54.6,48.5 55.6,49.5 57.34,49.5 J2.11@60.345,52.505 ; v1(61.2,68.45) 62.05,68.45 63.5,67 M1.198@63.5,65.6
  L1-Signal w0.15: X4.1@52.8,46.6 54.1,47.9 54.1,50.55 52.85,51.8 52.85,57.374 58.65,63.174 58.65,65.9 v1(61.2,68.45) 61.99,68.45 63.54,66.9 76.85,66.9 v1(77.9,67.95)
  Bottom Layer w0.25: U6.2@57.556,70.211 59.439,70.211 v1(61.2,68.45) ; U3.24@77.15,67.95 v1(77.9,67.95)
SPI_MOSI: J2.9 M1.200 U3.21 U6.5 X5.1 | length 69.8
  Top Layer w0.25: X5.1@51,47.6 53.2,47.6 54,48.4 54,49.1 55.418,50.518 57.088,50.518 J2.9@59.075,52.505 ; M1.200@64,65.6 64,66.8 v1(64.75,67.55)
  L1-Signal w0.15: X5.1@51,47.6 53.037,47.6 53.7,48.263 53.7,50.526 52.55,51.676 52.55,57.499 58.35,63.299 58.35,66.426 60.924,69 63.3,69 v1(64.75,67.55) 65.608,67.55 65.783,67.375 68.117,67.375 68.5,67.758 68.5,68.067 71.883,71.45 76.076,71.45 77,70.526 77,70.164 77.77,69.393 v1(78.007,69.393)
  Bottom Layer w0.25: U6.5@63.017,72.751 64.599,72.751 65.85,71.5 65.85,68.65 v1(64.75,67.55) ; U3.21@77.15,69.45 77.95,69.45 v1(78.007,69.393)
TOP_5V: C255.1 C258.2 D31.2 J16.L1 J16.U1 U68.6 X83.1 | length 23
  Top Layer w0.75: v1(15.85,17.8) 18.481,17.8 18.7,17.581 C255.1@18.7,16.677 X83.1@18.7,13.6
  Bottom Layer w0.4: 20.752,11.548 25.15,11.548
  Bottom Layer w0.5: v1(16.5,17.8) 16.519,17.819 16.984,17.819 17.45,18.285 C258.2@17.45,18.7 18.621,18.7 18.661,18.74 U68.6@18.661,18.745 ; X83.1@18.7,13.6 20.752,11.548 ; J16.L1@26.75,10.069 26.644,10.175 25.825,10.175 25.15,10.85 25.15,11.548 25.15,12.2 26.08,13.13 26.611,13.13 J16.U1@26.75,13.269
  Bottom Layer w0.75: v1(15.85,17.8) v1(16.5,17.8)
UART_1_CTS: M1.135 U16.7 | length 20.9
  Top Layer w0.15: U16.7@43.5,43.225 44.525,43.225 44.625,43.325 47.782,43.325 48.307,43.85 v1(48.8,43.85) ; M1.135@45.75,57.4 45.75,46.65 v1(46.21,46.19)
  Bottom Layer w0.15: v1(46.21,46.19) 47.11,46.19 48.75,44.55 48.75,43.9 v1(48.8,43.85)
UART_1_CTS_3V: R246.2 RA2.6 U16.15 U55.3 | length 91.3
  Top Layer w0.15: RA2.6@38.2,37.95 v1(38.2,38.918) 38.2,42.65 39.175,43.625 U16.15@42.1,43.625 ; v1(92.25,46.5) 93.083,46.5 93.183,46.4 93.186,46.4 93.392,46.194 U55.3@96.37,46.194
  L2-Signal w0.15: v1(38.2,38.918) 38.2,43.55 39.05,44.4 43.533,44.4 43.608,44.325 44.292,44.325 44.367,44.4 47.142,44.4 47.292,44.55 49.3,44.55 51.8,42.05 62.976,42.05 64.258,43.332 89.58,43.332 90,43.752 90.491,43.752 90.707,43.968 91.322,43.968 92.16,44.806 92.16,45.607 92.248,45.695 92.25,45.695 v1(92.25,46.5)
  Bottom Layer w0.15: v1(92.25,46.5) 92.229,46.521 91.829,46.521 91.3,47.05 91.3,48.7 90.4,49.6 90.4,51.45 91.425,52.475 96.467,52.475 96.875,52.067 96.875,51.243 97.075,51.043 97.075,50.743 R246.2@97.5,50.318
UART_1_RTS: M1.133 RA1.7 U16.3 | length 26.8
  Top Layer w0.15: U16.3@43.5,41.625 44.825,41.625 46.75,39.7 v1(46.75,38.4) RA1.7@46.75,37.4 ; v1(45.2,45.45) 45.2,46.176 45.2,57.35 M1.133@45.25,57.4
  Bottom Layer w0.15: v1(45.2,45.45) 47.725,42.925 47.725,39.375 v1(46.75,38.4)
UART_1_RTS_3V: R245.2 U16.19 U55.2 | length 79.4
  Top Layer w0.15: v1(39.9,40.95) 40.986,42.036 42.089,42.036 U16.19@42.1,42.025 ; v1(92.15,47.3) 92.272,47.3 92.572,47.6 93.187,47.6 93.437,47.35 96.255,47.35 U55.2@96.37,47.464
  L2-Signal w0.15: v1(36.6,41.5) 36.6,42.75 38.55,44.7 43.658,44.7 43.733,44.625 44.167,44.625 44.242,44.7 47.017,44.7 47.167,44.85 49.45,44.85 51.95,42.35 62.826,42.35 64.126,43.65 88,43.65 88.525,44.175 88.525,46.824 89.821,48.12 91.33,48.12 v1(92.15,47.3)
  Bottom Layer w0.15: v1(36.6,41.5) 39.35,41.5 v1(39.9,40.95) ; v1(92.15,47.3) 92.65,47.8 96.05,47.8 96.368,48.118 R245.2@97.5,48.118
UART_1_RX_3V: R248.2 RA2.5 U16.16 U54.3 | length 84.3
  Top Layer w0.15: RA2.5@39,37.95 v1(39,38.9) 39,42.75 39.475,43.225 U16.16@42.1,43.225 ; v1(91.25,40.85) 92.277,39.823 93.937,39.823 94.508,40.394 U54.3@96.347,40.394
  L2-Signal w0.15: v1(39,38.9) 39,43 39.3,43.3 50.1,43.3 51.65,41.75 63.121,41.75 64.403,43.032 89.168,43.032 89.6,42.6 89.6,41.65 90.4,40.85 v1(91.25,40.85)
  Bottom Layer w0.15: v1(91.25,40.85) 91.229,40.871 90.829,40.871 90.262,41.438 90.262,43.662 90.568,43.968 95.283,43.968 95.665,44.35 97.075,44.35 97.5,43.925 R248.2@97.5,43.718
UART_1_RXD: M1.129 U16.6 | length 23.1
  Top Layer w0.15: U16.6@43.5,42.825 45.783,42.825 45.983,43.025 48.975,43.025 49.45,43.5 49.45,49.15 46.8,51.8 v1(46.8,54.15) ; v1(44.2,55.4) 44.25,55.4 M1.129@44.25,57.4
  Bottom Layer w0.15: v1(44.2,55.4) 45.55,55.4 v1(46.8,54.15)
UART_1_TX_3V: R247.2 U16.20 U54.2 | length 72.3
  Top Layer w0.15: v1(40.8,40.8) 40.853,40.853 40.853,41.325 41.02,41.491 41.02,41.494 41.151,41.625 U16.20@42.1,41.625 ; v1(88.7,41.85) 89.5,42.65 93.763,42.65 94.749,41.664 U54.2@96.347,41.664
  L2-Signal w0.15: v1(40.8,40.8) 40.853,40.853 40.853,41.325 41.045,41.517 41.045,41.52 41.152,41.626 41.826,41.626 43.2,43 49.971,43 51.521,41.45 63.245,41.45 64.509,42.714 87.836,42.714 v1(88.7,41.85)
  Bottom Layer w0.15: v1(88.7,41.85) 89.962,43.112 89.962,44.612 90.7,45.35 93.305,45.35 93.307,45.348 95.393,45.348 95.395,45.35 95.5,45.35 96.068,45.918 R247.2@97.5,45.918
UART_1_TXD: M1.131 RA1.8 U16.2 | length 27.2
  Top Layer w0.15: U16.2@43.65,41.225 44.675,41.225 45.95,39.95 v1(45.95,38.4) RA1.8@45.95,37.4 ; v1(43.95,45.15) 44.75,45.95 44.75,49.5 M1.131@44.75,57.4
  Bottom Layer w0.15: v1(43.95,45.15) 44.758,45.15 47.4,42.508 47.4,39.85 v1(45.95,38.4)
UART_2_RTS: M1.141 RA1.5 U16.5 | length 31
  Top Layer w0.15: U16.5@43.5,42.425 45.225,42.425 48.35,39.3 RA1.5@48.35,37.4 49.15,37.4 50.7,38.95 50.7,41.55 50.1,42.15 50.1,50.258 50.025,50.333 50.025,50.767 50.1,50.842 50.1,52.3 47.25,55.15 M1.141@47.25,57.4
UART_2_RTS_3V: R242.2 U16.17 U51.2 | length 69.1
  Top Layer w0.15: v1(39.85,42.65) 39.92,42.72 40.375,42.72 40.48,42.825 U16.17@42.1,42.825 ; v1(92,34.7) 93.75,34.7 94.348,35.298 U51.2@96.191,35.298
  L2-Signal w0.15: v1(46.3,42.475) 46.422,42.475 46.611,42.286 48.944,42.286 49.083,42.425 49.675,42.425 52.05,40.05 65.649,40.05 67.449,38.25 78.349,38.25 82.549,34.05 91.35,34.05 v1(92,34.7)
  Bottom Layer w0.15: v1(39.85,42.65) 39.892,42.65 40.242,43 45.9,43 46.044,42.856 46.044,42.852 46.3,42.597 v1(46.3,42.475) ; v1(92,34.7) 95.95,34.7 96.75,33.9 R242.2@97.5,33.9
UART_2_RX_3V: R185.2 R186.2 RA2.7 U16.14 | length 72.7
  Top Layer w0.15: U16.14@41.95,44.025 38.675,44.025 37.4,42.75 RA2.7@37.4,37.95 37.4,37.35 37.55,37.2 44.8,37.2 45.35,36.65 48.95,36.65 51.75,39.45 52.678,39.45 52.978,39.15 v1(53.1,39.15) ; R185.2@90.95,28.15 R186.2@91.95,28.15
  Top Layer w0.25: R185.2@90.95,28.15 v1(90.95,28.887)
  L2-Signal w0.15: v1(53.1,39.15) 53.4,39.45 65.4,39.45 67.2,37.65 78.1,37.65 82.3,33.45 87.8,33.45 89.35,31.9 89.35,30.393 90.856,28.887 v1(90.95,28.887)
UART_2_RXD: M1.137 U16.8 | length 19.8
  Top Layer w0.15: U16.8@43.5,43.625 45.779,43.625 46.004,43.85 47.883,43.85 49.15,45.117 49.15,48.6 46.25,51.5 M1.137@46.25,57.4
UART_2_TX_3V: R189.2 U16.18 U50.2 | length 74.4
  Top Layer w0.15: v1(39.9,41.8) 39.938,41.8 40.343,42.205 40.605,42.205 40.825,42.425 U16.18@42.1,42.425 ; v1(90,31.25) 91.728,29.522 U50.2@96.191,29.522
  L2-Signal w0.15: v1(46.875,41.7) 48.348,41.7 48.499,41.851 49.825,41.851 51.926,39.75 65.524,39.75 67.324,37.95 78.224,37.95 82.424,33.75 88.4,33.75 90,32.15 v1(90,31.25)
  Bottom Layer w0.15: v1(39.9,41.8) 39.938,41.8 40.343,42.205 45.745,42.205 46.275,41.675 46.85,41.675 v1(46.875,41.7) ; v1(90,31.25) 89.55,30.8 89.55,30 90.05,29.5 R189.2@97.5,29.5
UART_2_TXD: M1.139 RA1.6 U16.4 | length 29.1
  Top Layer w0.15: U16.4@43.5,42.025 45.025,42.025 47.55,39.5 47.55,38.45 v1(47.5,38.4) 47.5,37.45 RA1.6@47.55,37.4 ; M1.139@46.75,57.4 46.75,55.05 49.8,52 49.8,50.967 49.725,50.892 49.725,50.208 49.8,50.133 49.8,41.65 49.25,41.1 v1(48.35,41.1)
  Bottom Layer w0.15: v1(47.5,38.4) 47.6,38.4 48.15,38.95 48.15,40.787 48.35,40.987 v1(48.35,41.1)
UART_3_RXD: J17.2 M1.147 Q15.1 R264.2 | length 72.8
  Top Layer w0.15: v1(49.15,58.65) 49.7,59.2 50.45,59.2 50.75,58.9 50.75,58.892 50.775,58.867 50.775,57.425 M1.147@50.75,57.4
  L3-Signal w0.15: v1(26.9,76.7) 26.9,75.85 27.2,75.55 32.25,75.55 v1(49.15,58.65)
  Bottom Layer w0.15: J17.2@19.1,54.9 19.1,56.05 20.5,57.45 47.95,57.45 v1(49.15,58.65) ; v1(26.9,76.7) 27.8,77.6 29.9,77.6 30.2,77.3 R264.2@30.2,76.65 31.775,76.65 Q15.1@32.375,76.05
UART_3_RXD_3V: J1.4 Q15.6 R271.2 | length 35.9
  Top Layer w0.15: J1.4@19.21,103.05 19.21,101.89 19.53,101.57 19.53,94.52 20.45,93.6 20.45,89.85 26.5,83.8 v1(26.5,77.6)
  Bottom Layer w0.15: v1(26.5,77.6) 26.3,77.4 26.3,75.671 26.95,75.021 27.367,75.021 27.389,75 28.75,75 R271.2@29.4,75.65 29.95,75.65 30.35,76.05 Q15.6@31.025,76.05
UART_3_TXD: J17.3 M1.149 Q15.4 R269.2 | length 74.1
  Top Layer w0.15: M1.149@51.25,57.4 51.275,57.425 51.275,58.825 v1(51.3,58.85)
  L3-Signal w0.15: v1(27.15,74.496) 27.173,74.473 27.5,74.8 30.85,74.8 48.35,57.3 50.526,57.3 51.3,58.074 v1(51.3,58.85)
  Bottom Layer w0.15: J17.3@21.64,54.9 21.64,56.04 22.05,56.45 27.603,56.45 28.103,56.95 28.228,57.075 34.16,57.075 35.34,57.075 49.525,57.075 v1(51.3,58.85) ; v1(27.15,74.496) 27.15,74.45 29.8,74.45 30.4,75.05 Q15.4@31.025,75.05 31.35,75.05 31.85,74.55 32.85,74.55 33,74.4 33.85,74.4 34.05,74.6 R269.2@34.5,74.6
UART_3_TXD_3V: J1.5 Q15.3 R270.2 | length 45.7
  Top Layer w0.15: J1.5@16.67,103.05 16.67,101.78 16.99,101.46 16.99,92.61 25.8,83.8 25.8,73.971 v1(25.821,73.971)
  L3-Signal w0.15: v1(33.75,75.05) 34.95,73.85 v1(35.05,73.85)
  Bottom Layer w0.15: v1(25.821,73.971) 28.629,73.971 R270.2@29.2,73.4 34.6,73.4 v1(35.05,73.85) ; Q15.3@32.375,75.05 v1(33.75,75.05)
USB1_CC1: J4.A5 U13.1 U15.2 U15.9 X24.1 | length 21.8
  Top Layer w0.15: J4.A5@7.35,49.1 v1(8.4,49.1)
  Bottom Layer w0.15: v1(8.4,49.1) 7.95,49.55 6.007,49.55 5.5,49.043 5.5,47.05 6.3,46.25 8.792,46.25 8.967,46.075 9.638,46.075 9.663,46.1 U15.2@10.128,46.1 11.495,46.1 11.52,46.075 12.598,46.075 12.648,46.125 13.725,46.125 16.15,48.55 X24.1@16.15,49.6 17,49.6 17.55,49.05 U13.1@18.2,49.05
USB1_CC2: J4.B5 U13.2 U15.1 U15.10 X23.1 | length 14.8
  Top Layer w0.15: J4.B5@7.35,46.1 8.7,46.1 v1(9.25,45.55) ; v1(13,45.6) v1(13,46.65)
  Bottom Layer w0.15: v1(9.25,45.55) 9.275,45.575 10.104,45.575 U15.1@10.128,45.6 U15.10@10.962,45.6 v1(13,45.6) ; v1(13,46.65) 14.65,48.3 X23.1@14.65,49.6 ; X23.1@14.767,50.074 15.343,50.65 16.536,50.65 17.736,49.45 U13.2@18.2,49.45
USB1_EN: M1.155 R84.2 U48.5 | length 39.5
  Top Layer w0.15: v1(49.75,56.125) 49.75,56.1 52.55,56.1 52.75,56.3 M1.155@52.75,57.4
  L2-Signal w0.15: v1@54.55,63.5 v1(54.5,63.45) 54.5,66.6 56.05,68.15 v1(58.3,68.15)
  L3-Signal w0.15: v1(49.75,56.125) 49.762,56.112 52.15,58.5 52.95,58.5 54.5,60.05 v1(54.5,63.45) ; v1(58.3,68.15) 59.75,68.15 63.25,64.65 63.25,63.15 64.75,61.65 65.013,61.65 v1(65.713,62.35)
  Bottom Layer w0.15: U48.5@65.6,61.35 65.6,62.25 65.7,62.35 v1(65.713,62.35) 66.018,62.35 66.918,63.25 67.55,63.25 68.05,63.75 68.05,64.4 67.45,65 67.443,64.993 R84.2@66.35,64.993
USB1_EN_3V: U14.3 U48.17 X20.1 | length 90.7
  L3-Signal w0.15: v1(7.1,38.5) 7.1,42 10.6,45.5 10.6,47.9 12.95,50.25 28.55,50.25 29.25,49.55 32.3,49.55 34.2,51.45 43.8,51.45 44.475,52.125 47.375,52.125 54.05,58.8 55.5,58.8 56.2,58.8 58.25,56.75 v1(58.25,56.05)
  Bottom Layer w0.15: v1(7.1,38.5) 8.95,38.5 10,37.45 10,32.092 9.433,31.525 9.425,31.525 9,31.1 9,29.15 8.45,28.6 U14.3@7.36,28.6 ; X20.1@7.386,27.22 U14.3@7.386,28.574 ; v1(58.25,56.05) 58.25,56.7 58.85,57.3 64.2,57.3 66,59.1 U48.17@66,59.95
USB1_ID: M1.161 R58.1 U13.9 X19.1 | length 56.5
  Top Layer w0.15: v1(51.45,51.1) 51.45,51.75 51.45,53.041 52.2,53.791 52.2,53.793 54.25,55.843 M1.161@54.25,57.4
  L3-Signal w0.15: v1(21.256,47.449) 21.832,48.025 44.575,48.025 47.85,51.3 49.744,51.3 51.25,51.3 v1(51.45,51.1)
  Bottom Layer w0.15: X19.1@10.45,43.6 12,43.6 14.2,45.8 20.143,45.8 21.25,46.907 v1@21.25,47.502 ; U13.9@19.45,48.5 19.95,48.5 20.1,48.35 20.1,47.9 20.41,47.59 21.115,47.59 v1(21.256,47.449) ; v1(51.45,51.1) 51.7,50.85 51.7,49.85 R58.1@51.7,49.35
USB1_N: L18.3 M1.163 | length 58.2
  Top Layer w0.2: v1(51.12,60.02) 51.196,59.943 51.479,59.943 52.24,59.182 54.268,59.182 54.825,58.625 54.825,58.424 54.8,58.399 54.8,57.45 M1.163@54.75,57.4
  Bottom Layer w0.2: L18.3@12.1,52.4 12.1,52.225 12.2,52.125 12.233,52.125 12.35,52.008 12.35,51.721 12.233,51.604 11.396,51.604 11.2,51.8 10.8,52.2 10.8,52.932 10.8,53.532 cw(c11,53.532) 11,53.732 11.986,53.732 ccw(c11.986,53.857) 12.111,53.857 12.111,54.107 ccw(c11.986,54.107) 11.986,54.232 11,54.232 cw(c11,54.432) 10.8,54.432 10.8,54.75 11.633,55.583 12.733,56.683 15.228,56.683 16.25,57.705 16.25,60.15 17.4,61.3 24.45,61.3 25.113,60.637 50.747,60.637 51.043,60.342 51.043,60.096 v1(51.12,60.02)
USB1_OC#: M1.157 R61.1 U14.4 X22.1 | length 78.9
  Top Layer w0.15: v1(48.85,56.45) 48.85,56 49.4,55.45 52.65,55.45 53.25,56.05 M1.157@53.25,57.4
  Bottom Layer w0.15: X22.1@3.45,27.6 3.45,28.5 ; R61.1@4.85,27.25 U14.4@4.85,28.6 3.55,28.6 3.45,28.5 ; v1(48.85,56.45) 48.525,56.775 48.125,56.775 47.818,56.775 35.216,56.775 34.284,56.775 28.352,56.775 21.9,50.323 21.9,47.133 20.267,45.5 14.8,45.5 12.025,42.725 5.349,42.725 1.5,38.876 1.5,29.532 2.532,28.5 3.45,28.5
USB1_P: L18.2 M1.165 | length 58.2
  Top Layer w0.2: v1(51.65,60.55) 51.727,60.473 51.727,60.191 52.385,59.532 54.412,59.532 55.175,58.77 55.175,58.424 55.2,58.399 55.2,57.45 M1.165@55.25,57.4
  Bottom Layer w0.2: L18.2@12.95,52.4 12.95,52.225 12.85,52.125 12.817,52.125 12.7,52.008 12.7,51.576 12.378,51.254 11.251,51.254 11.046,51.459 10.45,52.055 10.45,54.895 12.588,57.033 15.083,57.033 15.9,57.85 15.9,60.295 17.255,61.65 24.595,61.65 25.258,60.987 50.963,60.987 51.323,60.627 51.573,60.627 v1(51.65,60.55)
